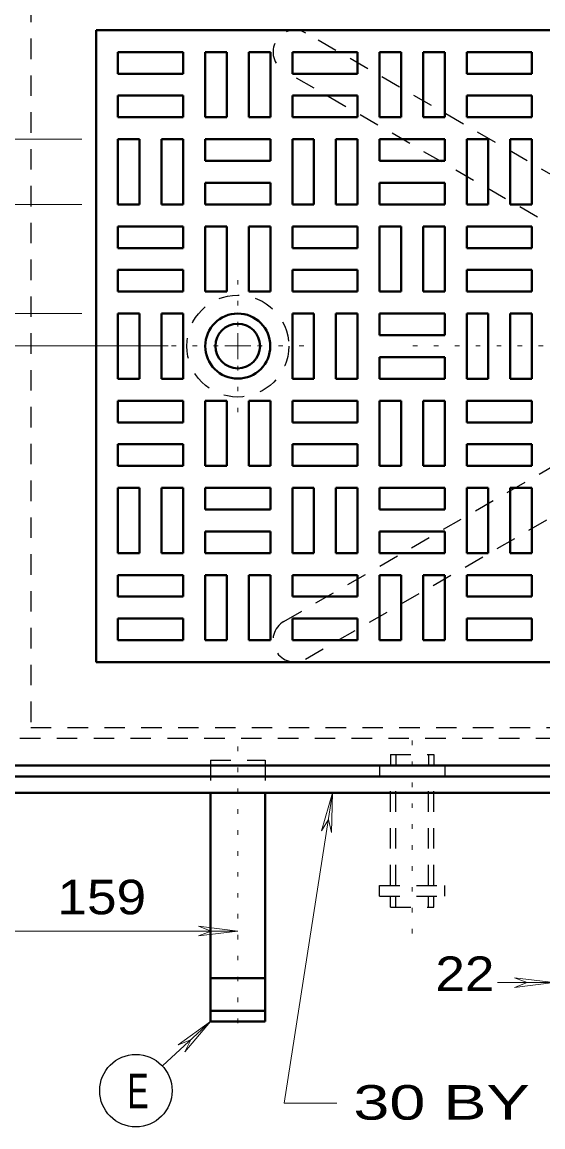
# Model space of a CAD drawing. Extents: x 312583 to 312854, y 144419 to 144597.
# Drawn here: x 312652.93 to 312664.38, y 144537.73 to 144562.03 of the extents above; entities that cross this region are included whole.
import ezdxf

# ---------------------------------------------------------------- set-up
doc = ezdxf.new("R2010")
doc.units = 0
doc.header["$LTSCALE"] = 0.3
doc.linetypes.add('DOTTED', pattern=[1.5, 0.3, -1.2])
doc.linetypes.add('SHORT_DASHED', pattern=[2.7, 1.5, -1.2])
doc.layers.add('1', color=7, linetype='Continuous', lineweight=13)

msp = doc.modelspace()

# ---------------------------------------------------------------- linework, layer by layer
at = {"layer": '1', "lineweight": 40}
for p, q in [((312654.5566, 144561.85), (312654.5566, 144547.9503)), ((312655.0396, 144561.367), (312656.4733, 144561.367)), ((312655.0396, 144560.8916), (312655.0396, 144561.367)), ((312656.4733, 144560.8916), (312656.4733, 144561.367)), ((312656.9563, 144561.367), (312656.9563, 144559.9333)), ((312656.9563, 144561.367), (312657.4316, 144561.367)), ((312657.4316, 144561.367), (312657.4316, 144559.9333)), ((312657.9146, 144561.367), (312657.9146, 144559.9333)), ((312657.9146, 144561.367), (312658.3899, 144561.367)), ((312658.3899, 144561.367), (312658.3899, 144559.9333)), ((312658.8729, 144561.367), (312660.3066, 144561.367)), ((312658.8729, 144560.8916), (312658.8729, 144561.367)), ((312660.3066, 144560.8916), (312660.3066, 144561.367)), ((312660.7896, 144561.367), (312660.7896, 144559.9333)), ((312660.7896, 144561.367), (312661.2649, 144561.367)), ((312661.2649, 144561.367), (312661.2649, 144559.9333)), ((312661.7479, 144561.367), (312661.7479, 144559.9333)), ((312661.7479, 144561.367), (312662.2233, 144561.367)), ((312662.2233, 144561.367), (312662.2233, 144559.9333)), ((312662.7063, 144561.367), (312664.1399, 144561.367)), ((312662.7063, 144560.8916), (312662.7063, 144561.367)), ((312664.1399, 144560.8916), (312664.1399, 144561.367)), ((312655.0396, 144560.8916), (312656.4733, 144560.8916)), ((312658.8729, 144560.8916), (312660.3066, 144560.8916)), ((312662.7063, 144560.8916), (312664.1399, 144560.8916)), ((312655.0396, 144560.4086), (312656.4733, 144560.4086)), ((312655.0396, 144559.9333), (312655.0396, 144560.4086)), ((312656.4733, 144559.9333), (312656.4733, 144560.4086)), ((312658.8729, 144560.4086), (312660.3066, 144560.4086)), ((312658.8729, 144559.9333), (312658.8729, 144560.4086)), ((312660.3066, 144559.9333), (312660.3066, 144560.4086)), ((312662.7063, 144560.4086), (312664.1399, 144560.4086)), ((312662.7063, 144559.9333), (312662.7063, 144560.4086)), ((312664.1399, 144559.9333), (312664.1399, 144560.4086)), ((312655.0396, 144559.9333), (312656.4733, 144559.9333)), ((312656.9563, 144559.9333), (312657.4316, 144559.9333)), ((312657.9146, 144559.9333), (312658.3899, 144559.9333)), ((312658.8729, 144559.9333), (312660.3066, 144559.9333)), ((312660.7896, 144559.9333), (312661.2649, 144559.9333)), ((312661.7479, 144559.9333), (312662.2233, 144559.9333)), ((312662.7063, 144559.9333), (312664.1399, 144559.9333)), ((312655.0396, 144559.4503), (312655.0396, 144558.0166)), ((312655.0396, 144559.4503), (312655.5149, 144559.4503)), ((312655.5149, 144559.4503), (312655.5149, 144558.0166)), ((312655.9979, 144559.4503), (312655.9979, 144558.0166)), ((312655.9979, 144559.4503), (312656.4733, 144559.4503)), ((312656.4733, 144559.4503), (312656.4733, 144558.0166)), ((312656.9563, 144559.4503), (312658.3899, 144559.4503)), ((312656.9563, 144558.975), (312656.9563, 144559.4503)), ((312658.3899, 144558.975), (312658.3899, 144559.4503)), ((312658.8729, 144559.4503), (312658.8729, 144558.0166)), ((312658.8729, 144559.4503), (312659.3483, 144559.4503)), ((312659.3483, 144559.4503), (312659.3483, 144558.0166)), ((312659.8313, 144559.4503), (312659.8313, 144558.0166)), ((312659.8313, 144559.4503), (312660.3066, 144559.4503)), ((312660.3066, 144559.4503), (312660.3066, 144558.0166)), ((312660.7896, 144559.4503), (312662.2233, 144559.4503)), ((312660.7896, 144558.975), (312660.7896, 144559.4503)), ((312662.2233, 144558.975), (312662.2233, 144559.4503)), ((312662.7063, 144559.4503), (312662.7063, 144558.0166)), ((312662.7063, 144559.4503), (312663.1816, 144559.4503)), ((312663.1816, 144559.4503), (312663.1816, 144558.0166)), ((312663.6646, 144559.4503), (312663.6646, 144558.0166)), ((312663.6646, 144559.4503), (312664.1399, 144559.4503)), ((312664.1399, 144559.4503), (312664.1399, 144558.0166)), ((312656.9563, 144558.975), (312658.3899, 144558.975)), ((312660.7896, 144558.975), (312662.2233, 144558.975)), ((312656.9563, 144558.492), (312658.3899, 144558.492)), ((312656.9563, 144558.0166), (312656.9563, 144558.492)), ((312658.3899, 144558.0166), (312658.3899, 144558.492)), ((312660.7896, 144558.492), (312662.2233, 144558.492)), ((312660.7896, 144558.0166), (312660.7896, 144558.492)), ((312662.2233, 144558.0166), (312662.2233, 144558.492)), ((312655.0396, 144558.0166), (312655.5149, 144558.0166)), ((312655.9979, 144558.0166), (312656.4733, 144558.0166)), ((312656.9563, 144558.0166), (312658.3899, 144558.0166)), ((312658.8729, 144558.0166), (312659.3483, 144558.0166)), ((312659.8313, 144558.0166), (312660.3066, 144558.0166)), ((312660.7896, 144558.0166), (312662.2233, 144558.0166)), ((312662.7063, 144558.0166), (312663.1816, 144558.0166)), ((312663.6646, 144558.0166), (312664.1399, 144558.0166)), ((312655.0396, 144557.5336), (312656.4733, 144557.5336)), ((312655.0396, 144557.0583), (312655.0396, 144557.5336)), ((312656.4733, 144557.0583), (312656.4733, 144557.5336)), ((312656.9563, 144557.5336), (312656.9563, 144556.1)), ((312656.9563, 144557.5336), (312657.4316, 144557.5336)), ((312657.4316, 144557.5336), (312657.4316, 144556.1)), ((312657.9146, 144557.5336), (312657.9146, 144556.1)), ((312657.9146, 144557.5336), (312658.3899, 144557.5336)), ((312658.3899, 144557.5336), (312658.3899, 144556.1)), ((312658.8729, 144557.5336), (312660.3066, 144557.5336)), ((312658.8729, 144557.0583), (312658.8729, 144557.5336)), ((312660.3066, 144557.0583), (312660.3066, 144557.5336)), ((312660.7896, 144557.5336), (312660.7896, 144556.1)), ((312660.7896, 144557.5336), (312661.2649, 144557.5336)), ((312661.2649, 144557.5336), (312661.2649, 144556.1)), ((312661.7479, 144557.5336), (312661.7479, 144556.1)), ((312661.7479, 144557.5336), (312662.2233, 144557.5336)), ((312662.2233, 144557.5336), (312662.2233, 144556.1)), ((312662.7063, 144557.5336), (312664.1399, 144557.5336)), ((312662.7063, 144557.0583), (312662.7063, 144557.5336)), ((312664.1399, 144557.0583), (312664.1399, 144557.5336)), ((312655.0396, 144557.0583), (312656.4733, 144557.0583)), ((312658.8729, 144557.0583), (312660.3066, 144557.0583)), ((312662.7063, 144557.0583), (312664.1399, 144557.0583)), ((312655.0396, 144556.5753), (312656.4733, 144556.5753)), ((312655.0396, 144556.1), (312655.0396, 144556.5753)), ((312656.4733, 144556.1), (312656.4733, 144556.5753)), ((312658.8729, 144556.5753), (312660.3066, 144556.5753)), ((312658.8729, 144556.1), (312658.8729, 144556.5753)), ((312660.3066, 144556.1), (312660.3066, 144556.5753)), ((312662.7063, 144556.5753), (312664.1399, 144556.5753)), ((312662.7063, 144556.1), (312662.7063, 144556.5753)), ((312664.1399, 144556.1), (312664.1399, 144556.5753)), ((312655.0396, 144556.1), (312656.4733, 144556.1)), ((312656.9563, 144556.1), (312657.4316, 144556.1)), ((312657.9146, 144556.1), (312658.3899, 144556.1)), ((312658.8729, 144556.1), (312660.3066, 144556.1)), ((312660.7896, 144556.1), (312661.2649, 144556.1)), ((312661.7479, 144556.1), (312662.2233, 144556.1)), ((312662.7063, 144556.1), (312664.1399, 144556.1)), ((312655.0396, 144555.617), (312655.0396, 144554.1833)), ((312655.0396, 144555.617), (312655.5149, 144555.617)), ((312655.5149, 144555.617), (312655.5149, 144554.1833)), ((312655.9979, 144555.617), (312655.9979, 144554.1833)), ((312655.9979, 144555.617), (312656.4733, 144555.617)), ((312656.4733, 144555.617), (312656.4733, 144554.1833)), ((312658.8729, 144555.617), (312658.8729, 144554.1833)), ((312658.8729, 144555.617), (312659.3483, 144555.617)), ((312659.3483, 144555.617), (312659.3483, 144554.1833)), ((312659.8313, 144555.617), (312659.8313, 144554.1833)), ((312659.8313, 144555.617), (312660.3066, 144555.617)), ((312660.3066, 144555.617), (312660.3066, 144554.1833)), ((312660.7896, 144555.617), (312662.2233, 144555.617)), ((312660.7896, 144555.1416), (312660.7896, 144555.617)), ((312662.2233, 144555.1416), (312662.2233, 144555.617)), ((312662.7063, 144555.617), (312662.7063, 144554.1833)), ((312662.7063, 144555.617), (312663.1816, 144555.617)), ((312663.1816, 144555.617), (312663.1816, 144554.1833)), ((312663.6646, 144555.617), (312663.6646, 144554.1833)), ((312663.6646, 144555.617), (312664.1399, 144555.617)), ((312664.1399, 144555.617), (312664.1399, 144554.1833)), ((312660.7896, 144555.1416), (312662.2233, 144555.1416)), ((312660.7896, 144554.6586), (312662.2233, 144554.6586)), ((312660.7896, 144554.1833), (312660.7896, 144554.6586)), ((312662.2233, 144554.1833), (312662.2233, 144554.6586)), ((312655.0396, 144554.1833), (312655.5149, 144554.1833)), ((312655.9979, 144554.1833), (312656.4733, 144554.1833)), ((312658.8729, 144554.1833), (312659.3483, 144554.1833)), ((312659.8313, 144554.1833), (312660.3066, 144554.1833)), ((312660.7896, 144554.1833), (312662.2233, 144554.1833)), ((312662.7063, 144554.1833), (312663.1816, 144554.1833)), ((312663.6646, 144554.1833), (312664.1399, 144554.1833)), ((312655.0396, 144553.7003), (312656.4733, 144553.7003)), ((312655.0396, 144553.225), (312655.0396, 144553.7003)), ((312656.4733, 144553.225), (312656.4733, 144553.7003)), ((312656.9563, 144553.7003), (312656.9563, 144552.2666)), ((312656.9563, 144553.7003), (312657.4316, 144553.7003)), ((312657.4316, 144553.7003), (312657.4316, 144552.2666)), ((312657.9146, 144553.7003), (312657.9146, 144552.2666)), ((312657.9146, 144553.7003), (312658.3899, 144553.7003)), ((312658.3899, 144553.7003), (312658.3899, 144552.2666)), ((312658.8729, 144553.7003), (312660.3066, 144553.7003)), ((312658.8729, 144553.225), (312658.8729, 144553.7003)), ((312660.3066, 144553.225), (312660.3066, 144553.7003)), ((312660.7896, 144553.7003), (312660.7896, 144552.2666)), ((312660.7896, 144553.7003), (312661.2649, 144553.7003)), ((312661.2649, 144553.7003), (312661.2649, 144552.2666)), ((312661.7479, 144553.7003), (312661.7479, 144552.2666)), ((312661.7479, 144553.7003), (312662.2233, 144553.7003)), ((312662.2233, 144553.7003), (312662.2233, 144552.2666)), ((312662.7063, 144553.7003), (312664.1399, 144553.7003)), ((312662.7063, 144553.225), (312662.7063, 144553.7003)), ((312664.1399, 144553.225), (312664.1399, 144553.7003)), ((312655.0396, 144553.225), (312656.4733, 144553.225)), ((312658.8729, 144553.225), (312660.3066, 144553.225)), ((312662.7063, 144553.225), (312664.1399, 144553.225)), ((312655.0396, 144552.742), (312656.4733, 144552.742)), ((312655.0396, 144552.2666), (312655.0396, 144552.742)), ((312656.4733, 144552.2666), (312656.4733, 144552.742)), ((312658.8729, 144552.742), (312660.3066, 144552.742)), ((312658.8729, 144552.2666), (312658.8729, 144552.742)), ((312660.3066, 144552.2666), (312660.3066, 144552.742)), ((312662.7063, 144552.742), (312664.1399, 144552.742)), ((312662.7063, 144552.2666), (312662.7063, 144552.742)), ((312664.1399, 144552.2666), (312664.1399, 144552.742)), ((312655.0396, 144552.2666), (312656.4733, 144552.2666)), ((312656.9563, 144552.2666), (312657.4316, 144552.2666)), ((312657.9146, 144552.2666), (312658.3899, 144552.2666)), ((312658.8729, 144552.2666), (312660.3066, 144552.2666)), ((312660.7896, 144552.2666), (312661.2649, 144552.2666)), ((312661.7479, 144552.2666), (312662.2233, 144552.2666)), ((312662.7063, 144552.2666), (312664.1399, 144552.2666)), ((312655.0396, 144551.7836), (312655.0396, 144550.35)), ((312655.0396, 144551.7836), (312655.5149, 144551.7836)), ((312655.5149, 144551.7836), (312655.5149, 144550.35)), ((312655.9979, 144551.7836), (312655.9979, 144550.35)), ((312655.9979, 144551.7836), (312656.4733, 144551.7836)), ((312656.4733, 144551.7836), (312656.4733, 144550.35)), ((312656.9563, 144551.7836), (312658.3899, 144551.7836)), ((312656.9563, 144551.3083), (312656.9563, 144551.7836)), ((312658.3899, 144551.3083), (312658.3899, 144551.7836)), ((312658.8729, 144551.7836), (312658.8729, 144550.35)), ((312658.8729, 144551.7836), (312659.3483, 144551.7836)), ((312659.3483, 144551.7836), (312659.3483, 144550.35)), ((312659.8313, 144551.7836), (312659.8313, 144550.35)), ((312659.8313, 144551.7836), (312660.3066, 144551.7836)), ((312660.3066, 144551.7836), (312660.3066, 144550.35)), ((312660.7896, 144551.7836), (312662.2233, 144551.7836)), ((312660.7896, 144551.3083), (312660.7896, 144551.7836)), ((312662.2233, 144551.3083), (312662.2233, 144551.7836)), ((312662.7063, 144551.7836), (312662.7063, 144550.35)), ((312662.7063, 144551.7836), (312663.1816, 144551.7836)), ((312663.1816, 144551.7836), (312663.1816, 144550.35)), ((312663.6646, 144551.7836), (312663.6646, 144550.35)), ((312663.6646, 144551.7836), (312664.1399, 144551.7836)), ((312664.1399, 144551.7836), (312664.1399, 144550.35)), ((312656.9563, 144551.3083), (312658.3899, 144551.3083)), ((312660.7896, 144551.3083), (312662.2233, 144551.3083)), ((312656.9563, 144550.8253), (312658.3899, 144550.8253)), ((312656.9563, 144550.35), (312656.9563, 144550.8253)), ((312658.3899, 144550.35), (312658.3899, 144550.8253)), ((312660.7896, 144550.8253), (312662.2233, 144550.8253)), ((312660.7896, 144550.35), (312660.7896, 144550.8253)), ((312662.2233, 144550.35), (312662.2233, 144550.8253)), ((312655.0396, 144550.35), (312655.5149, 144550.35)), ((312655.9979, 144550.35), (312656.4733, 144550.35)), ((312656.9563, 144550.35), (312658.3899, 144550.35)), ((312658.8729, 144550.35), (312659.3483, 144550.35)), ((312659.8313, 144550.35), (312660.3066, 144550.35)), ((312660.7896, 144550.35), (312662.2233, 144550.35)), ((312662.7063, 144550.35), (312663.1816, 144550.35)), ((312663.6646, 144550.35), (312664.1399, 144550.35)), ((312655.0396, 144549.867), (312656.4733, 144549.867)), ((312655.0396, 144549.3916), (312655.0396, 144549.867)), ((312656.4733, 144549.3916), (312656.4733, 144549.867)), ((312656.9563, 144549.867), (312656.9563, 144548.4333)), ((312656.9563, 144549.867), (312657.4316, 144549.867)), ((312657.4316, 144549.867), (312657.4316, 144548.4333)), ((312657.9146, 144549.867), (312657.9146, 144548.4333)), ((312657.9146, 144549.867), (312658.3899, 144549.867)), ((312658.3899, 144549.867), (312658.3899, 144548.4333)), ((312658.8729, 144549.867), (312660.3066, 144549.867)), ((312658.8729, 144549.3916), (312658.8729, 144549.867)), ((312660.3066, 144549.3916), (312660.3066, 144549.867)), ((312660.7896, 144549.867), (312660.7896, 144548.4333)), ((312660.7896, 144549.867), (312661.2649, 144549.867)), ((312661.2649, 144549.867), (312661.2649, 144548.4333)), ((312661.7479, 144549.867), (312661.7479, 144548.4333)), ((312661.7479, 144549.867), (312662.2233, 144549.867)), ((312662.2233, 144549.867), (312662.2233, 144548.4333)), ((312662.7063, 144549.867), (312664.1399, 144549.867)), ((312662.7063, 144549.3916), (312662.7063, 144549.867)), ((312664.1399, 144549.3916), (312664.1399, 144549.867)), ((312655.0396, 144549.3916), (312656.4733, 144549.3916)), ((312658.8729, 144549.3916), (312660.3066, 144549.3916)), ((312662.7063, 144549.3916), (312664.1399, 144549.3916)), ((312655.0396, 144548.9086), (312656.4733, 144548.9086)), ((312655.0396, 144548.4333), (312655.0396, 144548.9086)), ((312656.4733, 144548.4333), (312656.4733, 144548.9086)), ((312658.8729, 144548.9086), (312660.3066, 144548.9086)), ((312658.8729, 144548.4333), (312658.8729, 144548.9086)), ((312660.3066, 144548.4333), (312660.3066, 144548.9086)), ((312662.7063, 144548.9086), (312664.1399, 144548.9086)), ((312662.7063, 144548.4333), (312662.7063, 144548.9086)), ((312664.1399, 144548.4333), (312664.1399, 144548.9086)), ((312655.0396, 144548.4333), (312656.4733, 144548.4333)), ((312656.9563, 144548.4333), (312657.4316, 144548.4333)), ((312657.9146, 144548.4333), (312658.3899, 144548.4333)), ((312658.8729, 144548.4333), (312660.3066, 144548.4333)), ((312660.7896, 144548.4333), (312661.2649, 144548.4333)), ((312661.7479, 144548.4333), (312662.2233, 144548.4333)), ((312662.7063, 144548.4333), (312664.1399, 144548.4333)), ((312654.5566, 144547.9503), (312685.7063, 144547.9503)), ((312652.2796, 144545.681), (312687.9833, 144545.681)), ((312652.0419, 144545.4356), (312688.2209, 144545.4356)), ((312651.6816, 144545.0753), (312688.5813, 144545.0753)), ((312657.0713, 144545.0753), (312657.0713, 144540.046)), ((312658.2749, 144545.0753), (312658.2749, 144540.046)), ((312657.0713, 144541.0043), (312658.2749, 144541.0043)), ((312657.0713, 144540.2836), (312658.2749, 144540.2836)), ((312657.0713, 144540.046), (312658.2749, 144540.046))]:
    msp.add_line(p, q, dxfattribs=at)
at = {"layer": '1', "linetype": 'SHORT_DASHED', "lineweight": 25}
for p, q in [((312658.6889, 144548.8473), (312681.0986, 144561.7886)), ((312681.5739, 144548.8473), (312659.1643, 144561.7886)), ((312681.0986, 144548.0193), (312658.6889, 144560.953)), ((312659.1643, 144548.0193), (312681.5739, 144560.953)), ((312652.8853, 144546.279), (312687.3853, 144546.279)), ((312661.0273, 144545.9186), (312661.9856, 144545.9186)), ((312661.0273, 144545.9186), (312661.0273, 144545.681)), ((312661.1499, 144545.9186), (312661.1499, 144545.681)), ((312661.8629, 144545.9186), (312661.8629, 144545.681)), ((312661.9856, 144545.9186), (312661.9856, 144545.681)), ((312657.0713, 144545.796), (312658.2749, 144545.796)), ((312657.0713, 144545.796), (312657.0713, 144545.0753)), ((312658.2749, 144545.796), (312658.2749, 144545.0753)), ((312660.7896, 144545.681), (312662.2233, 144545.681)), ((312660.7896, 144545.681), (312660.7896, 144545.4356)), ((312662.2233, 144545.681), (312662.2233, 144545.4356)), ((312661.0273, 144543.0436), (312661.0273, 144545.4356)), ((312661.1499, 144543.0436), (312661.1499, 144545.4356)), ((312661.8629, 144543.0436), (312661.8629, 144545.4356)), ((312661.9856, 144543.0436), (312661.9856, 144545.4356)), ((312660.7896, 144543.0436), (312662.2233, 144543.0436)), ((312660.7896, 144542.806), (312660.7896, 144543.0436)), ((312662.2233, 144542.806), (312662.2233, 144543.0436)), ((312660.7896, 144542.806), (312662.2233, 144542.806)), ((312661.0273, 144542.5606), (312661.0273, 144542.806)), ((312661.1499, 144542.5606), (312661.1499, 144542.806)), ((312661.8629, 144542.5606), (312661.8629, 144542.806)), ((312661.9856, 144542.5606), (312661.9856, 144542.806)), ((312661.0273, 144542.5606), (312661.9856, 144542.5606))]:
    msp.add_line(p, q, dxfattribs=at)
at = {"layer": '1'}
for p, q in [((312660.7896, 144559.9333), (312660.7896, 144560.102)), ((312654.2423, 144559.4503), (312645.0116, 144559.4503)), ((312654.2423, 144558.0166), (312641.7609, 144558.0166)), ((312654.2423, 144555.617), (312645.0116, 144555.617)), ((312657.6769, 144554.904), (312657.6769, 144555.1876)), ((312656.1436, 144554.904), (312639.6219, 144554.904)), ((312657.6769, 144554.904), (312657.3856, 144554.904)), ((312657.6769, 144554.904), (312657.9606, 144554.904)), ((312657.6769, 144554.904), (312657.6769, 144554.6126)), ((312660.7896, 144552.2666), (312660.7896, 144552.4353)), ((312659.7546, 144545.0753), (312659.5169, 144544.2396)), ((312659.7546, 144545.0753), (312659.7316, 144544.209)), ((312659.5169, 144544.2396), (312659.6703, 144544.4926)), ((312659.7316, 144544.209), (312659.6703, 144544.4926)), ((312651.6816, 144542.0393), (312657.6769, 144542.0393)), ((312656.8106, 144542.1466), (312657.0866, 144542.0393)), ((312657.6769, 144542.0393), (312656.8106, 144542.1466)), ((312656.8106, 144541.932), (312657.0866, 144542.0393)), ((312657.6769, 144542.0393), (312656.8106, 144541.932)), ((312663.3809, 144540.9046), (312664.6229, 144540.9046)), ((312663.7566, 144541.012), (312664.0326, 144540.9046)), ((312664.6229, 144540.9046), (312663.7566, 144541.012)), ((312663.7566, 144540.7973), (312664.0326, 144540.9046)), ((312664.6229, 144540.9046), (312663.7566, 144540.7973)), ((312656.0209, 144539.0723), (312657.0713, 144540.046)), ((312657.0713, 144540.046), (312656.3659, 144539.54)), ((312657.0713, 144540.046), (312656.5116, 144539.379)), ((312656.3659, 144539.54), (312656.6419, 144539.6473)), ((312656.5116, 144539.379), (312656.6419, 144539.6473))]:
    msp.add_line(p, q, dxfattribs=at)
at = {"layer": '1', "linetype": 'DOTTED'}
for p, q in [((312657.6769, 144555.3333), (312657.6769, 144556.491)), ((312657.2399, 144554.904), (312656.1436, 144554.904)), ((312658.1063, 144554.904), (312659.2409, 144554.904)), ((312668.9853, 144554.904), (312661.3186, 144554.904)), ((312657.6769, 144554.467), (312657.6769, 144553.3553)), ((312661.5103, 144541.9856), (312661.5103, 144546.4706)), ((312657.6769, 144546.095), (312657.6769, 144539.701))]:
    msp.add_line(p, q, dxfattribs=at)
at = {"layer": '1', "linetype": 'SHORT_DASHED', "lineweight": 25}
msp.add_lwpolyline([(312653.1229, 144563.2836), (312653.1229, 144546.5166), (312687.1399, 144546.5166)], dxfattribs=at)
at = {"layer": '1', "lineweight": 40}
msp.add_lwpolyline([(312654.5566, 144561.85), (312685.7063, 144561.85), (312685.7063, 144547.9503)], dxfattribs=at)
at = {"layer": '1'}
msp.add_lwpolyline([(312659.8543, 144538.252), (312658.6966, 144538.252), (312659.7546, 144545.0753)], dxfattribs=at)
at = {"layer": '1', "linetype": 'SHORT_DASHED', "lineweight": 25}
msp.add_circle((312657.6731, 144554.9021), 1.1201, dxfattribs=at)
at = {"layer": '1', "lineweight": 40}
for radius in [0.7155, 0.4899]:
    msp.add_circle((312657.6731, 144554.9021), radius, dxfattribs=at)
at = {"layer": '1', "lineweight": 25}
msp.add_circle((312655.4335, 144538.528), 0.7964, dxfattribs=at)
at = {"layer": '1', "linetype": 'SHORT_DASHED', "lineweight": 25}
for centre, start, end in [((312658.9276, 144561.3708), 59.99927, 239.99927), ((312658.9276, 144548.4333), 120.00073, 300.00073)]:
    msp.add_arc(centre, 0.4792, start, end, dxfattribs=at)

# ---------------------------------------------------------------- texts
at = {"layer": '1'}
for s, width, p in [('159 ', 1.15, (312653.7083, 144542.4064)), ('22 ', 1.15, (312662.0164, 144540.7196)), ('E', 0.7, (312655.2422, 144538.1404)), ("30 BY 30 BY 6 MM  's @ 3 KG/M  's &", 1.4, (312660.2146, 144537.8906))]:
    msp.add_text(s, height=0.76, dxfattribs=dict(at, width=width)).set_placement(p)

doc.saveas('drawing.dxf')
